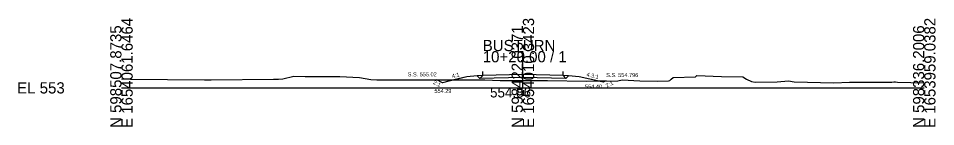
# Model space of a CAD drawing. Extents: x -26 to 1403, y -10 to 2017.
# Drawn here: x -25.7 to 202.8, y 490.3 to 517.4 of the extents above; entities that cross this region are included whole.
import ezdxf

# ---------------------------------------------------------------- set-up
doc = ezdxf.new("R2010")
doc.units = 0
for name, color, linetype in [('Exist Cross Section Cell', 7, 'Continuous'), ('Exist XS Center Line Elevation Label', 7, 'Continuous'), ('Exist XS Ground Line', 7, 'Continuous'), ('Prop XS Ditch Slope Text', 7, 'Continuous'), ('Prop XS Earthwork Shape', 7, 'Continuous'), ('Prop XS EOT Tick Mark', 7, 'Continuous'), ('Prop XS Finish Grade', 7, 'Continuous'), ('Prop XS Finish Grade Earthwork', 7, 'Continuous'), ('Prop XS Finish Grade Pavement', 7, 'Continuous'), ('Prop XS Label Text', 7, 'Continuous'), ('Prop XS Pvmt Edge Slope', 7, 'Continuous'), ('Prop XS Subgrade Earthwork', 7, 'Continuous')]:
    doc.layers.add(name, color=color, linetype=linetype)

msp = doc.modelspace()

# ---------------------------------------------------------------- linework, layer by layer
at = {"layer": 'Exist Cross Section Cell'}
for p, q in [((100, 500), (100, 509.18)), ((0, 500), (100, 500)), ((100, 500), (200, 500))]:
    msp.add_line(p, q, dxfattribs=at)
at = {"layer": 'Exist XS Ground Line'}
for p, q in [((40.18, 502.23), (42.95, 502.9)), ((42.95, 502.9), (45.73, 502.83)), ((45.73, 502.83), (46.18, 502.84)), ((46.18, 502.84), (47.01, 502.83)), ((47.01, 502.83), (54.42, 502.86)), ((54.42, 502.86), (59.27, 502.58)), ((143, 502.74), (143.3, 503.06)), ((143.3, 503.06), (149.48, 502.85)), ((149.48, 502.85), (154.78, 502.74)), ((0, 502.29), (2.24, 502.19)), ((2.24, 502.19), (20.69, 502)), ((20.69, 502), (22.33, 501.98)), ((22.33, 501.98), (37.91, 502.16)), ((37.91, 502.16), (39.16, 502.14)), ((39.16, 502.14), (40.18, 502.23)), ((59.27, 502.58), (62.14, 502.06)), ((62.14, 502.06), (63.6, 501.97)), ((63.6, 501.97), (72.31, 501.97)), ((72.31, 501.97), (73.89, 502.01)), ((73.89, 502.01), (78.2, 502.03)), ((78.2, 502.03), (87.39, 501.97)), ((87.39, 501.97), (90.54, 501.99)), ((90.54, 501.99), (94.35, 501.88)), ((94.35, 501.88), (100, 501.86)), ((100, 501.86), (106.16, 501.83)), ((106.16, 501.83), (115.83, 501.69)), ((115.83, 501.69), (123.63, 501.8)), ((123.63, 501.8), (124.73, 502.03)), ((124.73, 502.03), (129.15, 501.72)), ((129.15, 501.72), (133.65, 501.64)), ((133.65, 501.64), (136.25, 501.72)), ((136.25, 501.72), (136.58, 501.87)), ((136.58, 501.87), (136.92, 502.18)), ((136.92, 502.18), (137.46, 502.56)), ((137.46, 502.56), (143, 502.74)), ((154.78, 502.74), (155.69, 502.18)), ((155.69, 502.18), (156.93, 501.59)), ((156.93, 501.59), (157.87, 501.43)), ((157.87, 501.43), (163.33, 501.53)), ((163.33, 501.53), (166.14, 501.77)), ((166.14, 501.77), (167.59, 501.52)), ((167.59, 501.52), (177.47, 501.29)), ((177.47, 501.29), (181.39, 501.39)), ((181.39, 501.39), (191.9, 501.46)), ((191.9, 501.46), (192.4, 501.47)), ((192.4, 501.47), (192.81, 501.49)), ((192.81, 501.49), (193.36, 501.4)), ((193.36, 501.4), (200, 501.28))]:
    msp.add_line(p, q, dxfattribs=at)
at = {"layer": 'Prop XS Earthwork Shape'}
for points in [[(118.58, 501.73), (114, 502.79), (111.41, 503), (110.73, 502.35), (100, 502.56), (89.27, 502.35), (88.59, 503), (86, 502.79), (82.82, 502), (87.39, 501.97), (90.54, 501.99), (94.35, 501.88), (100, 501.86), (106.16, 501.83), (115.83, 501.69)], [(78.53, 502.03), (82.82, 502), (80, 501.29)], [(118.58, 501.73), (120.72, 501.76), (120, 501.4)]]:
    msp.add_lwpolyline(points, close=True, dxfattribs=at)
at = {"layer": 'Prop XS EOT Tick Mark'}
for p, q in [((90, 503.11), (90, 504.11)), ((110, 503.11), (110, 504.11))]:
    msp.add_line(p, q, dxfattribs=at)
at = {"layer": 'Prop XS Finish Grade'}
for p, q in [((90, 503.11), (88.59, 503)), ((111.41, 503), (110, 503.11))]:
    msp.add_line(p, q, dxfattribs=at)
at = {"layer": 'Prop XS Finish Grade Earthwork'}
for p, q in [((86, 502.79), (80, 501.29)), ((88.59, 503), (86, 502.79)), ((114, 502.79), (111.41, 503)), ((120, 501.4), (114, 502.79)), ((80, 501.29), (78.53, 502.03)), ((120.72, 501.76), (120, 501.4))]:
    msp.add_line(p, q, dxfattribs=at)
at = {"layer": 'Prop XS Finish Grade Pavement'}
for p, q in [((100, 503.31), (90, 503.11)), ((110, 503.11), (100, 503.31))]:
    msp.add_line(p, q, dxfattribs=at)
at = {"layer": 'Prop XS Pvmt Edge Slope'}
for p, q in [((89.27, 502.35), (90, 503.11)), ((110.73, 502.35), (110, 503.11))]:
    msp.add_line(p, q, dxfattribs=at)
at = {"layer": 'Prop XS Subgrade Earthwork'}
for p, q in [((88.59, 503), (89.27, 502.35)), ((111.41, 503), (110.73, 502.35)), ((100, 502.56), (89.27, 502.35)), ((110.73, 502.35), (100, 502.56))]:
    msp.add_line(p, q, dxfattribs=at)

# ---------------------------------------------------------------- texts
at = {"layer": 'Exist Cross Section Cell'}
for s, p in [('E 1654061.6464', (2.8, 490)), ('E 1654010.3423', (102.8, 490)), ('E 1653959.0382', (202.8, 490)), ('N 598507.8735', (0, 490)), ('N 598422.0371', (100, 490)), ('N 598336.2006', (200, 490))]:
    msp.add_text(s, height=2.8, rotation=90, dxfattribs=at).set_placement(p)
for s, p in [('BUSTURN', (90, 509.18)), ('10+20.00 / 1', (90, 506.38)), ('EL 553', (-26, 498.6))]:
    msp.add_text(s, height=2.8, dxfattribs=at).set_placement(p)
at = {"layer": 'Exist XS Center Line Elevation Label'}
msp.add_text('554.86', height=2.5, dxfattribs=at).set_placement((91.82, 497.61))
at = {"layer": 'Prop XS Ditch Slope Text'}
for s, rotation, p in [('4:1', 14.0362, (82.43, 502.41)), ('4.3:1', 346.9149, (115.79, 502.92)), ('2:1', 333.4349, (77.56, 501.05)), ('2:1', 26.5651, (120.93, 500.06))]:
    msp.add_text(s, height=1, rotation=rotation, dxfattribs=at).set_placement(p)
for s, p in [('554.40', (115.49, 499.83)), ('554.29', (77.97, 498.73))]:
    msp.add_text(s, height=1, dxfattribs=at).set_placement(p)
at = {"layer": 'Prop XS Label Text'}
for s, p in [('S.S. 555.02', (71.32, 502.88)), ('S.S. 554.796', (120.76, 502.7))]:
    msp.add_text(s, height=1, dxfattribs=at).set_placement(p)

doc.saveas('drawing.dxf')
